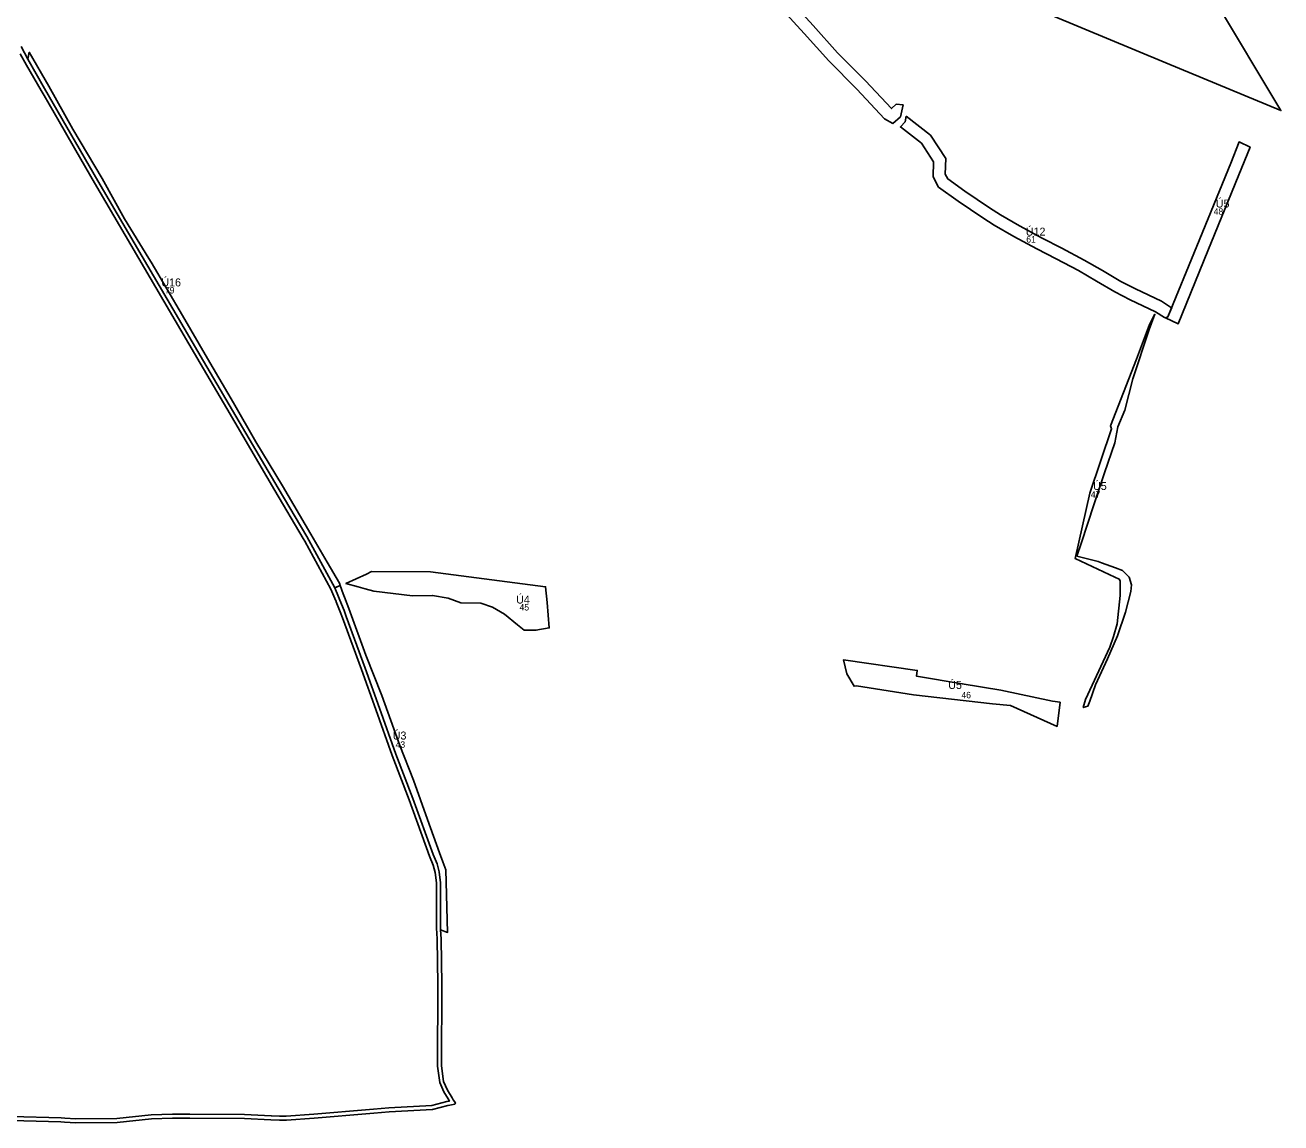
# Model space of a CAD drawing. Extents: x -521621 to -516857, y -1190025 to -1185894.
# Drawn here: x -519468 to -517899, y -1190007 to -1188636 of the extents above; entities that cross this region are included whole.
import ezdxf

# ---------------------------------------------------------------- set-up
doc = ezdxf.new("R2010")
doc.units = 0
for name, color, linetype in [('VPO_id', 7, 'Continuous'), ('VPO_n', 7, 'Continuous'), ('VPS_n', 7, 'Continuous')]:
    doc.layers.add(name, color=color, linetype=linetype)

msp = doc.modelspace()

# ---------------------------------------------------------------- linework, layer by layer
at = {"layer": 'VPO_n'}
for points in [[(-518107.5, -1188434.2), (-518094.9, -1188429), (-518088.8, -1188444.4), (-518071, -1188471), (-517982, -1188604), (-517899.2, -1188742.7), (-518042.7, -1188683.1), (-518186.2, -1188623.6), (-518130.3, -1188487.5)], [(-519313.1, -1188927.4), (-519310.2, -1188932.1), (-519271.2, -1188998.6), (-519239.8, -1189052.4), (-519207.6, -1189107.7), (-519179.5, -1189156.4), (-519146.3, -1189211.4), (-519110.8, -1189271.6), (-519090.3, -1189306.6), (-519075.2, -1189333), (-519074.1, -1189335.9), (-519080.9, -1189338.7), (-519116, -1189274.6), (-519151.5, -1189214.4), (-519245, -1189055.5), (-519376.8, -1188830.4), (-519443.4, -1188715.1), (-519464.3, -1188678.6), (-519462.5, -1188669.8), (-519438.2, -1188712.2), (-519408.1, -1188765.7), (-519371.6, -1188827.4), (-519343.6, -1188877.7)], [(-518367.1, -1188749.7), (-518337, -1188773.2), (-518317.9, -1188802.4), (-518318.6, -1188822), (-518315.3, -1188828), (-518293.9, -1188843.3), (-518263, -1188864), (-518249.5, -1188872.8), (-518225.6, -1188886.7), (-518197.2, -1188902), (-518173, -1188914.4), (-518144.8, -1188929.5), (-518122, -1188942.6), (-518099.3, -1188956), (-518080.9, -1188965.5), (-518048.5, -1188980.7), (-518037.1, -1188988.1), (-518035.5, -1188988.8), (-518040.2, -1189000.4), (-518043.4, -1189001.7), (-518044.4, -1189001.2), (-518055.7, -1188993.9), (-518087.5, -1188979), (-518106.5, -1188969.1), (-518129.5, -1188955.6), (-518152.1, -1188942.6), (-518180, -1188927.7), (-518204.1, -1188915.2), (-518232.9, -1188899.8), (-518257.4, -1188885.6), (-518271.3, -1188876.5), (-518302.4, -1188855.7), (-518326.9, -1188838.2), (-518333.7, -1188825.5), (-518333.1, -1188806.7), (-518348.2, -1188783.4), (-518374.4, -1188763), (-518368.5, -1188756.8)], [(-518040.2, -1189000.4), (-518004.2, -1188912.1), (-517961.8, -1188808.2), (-517951.3, -1188781.9), (-517937.7, -1188788.3), (-517947.9, -1188813.9), (-517990.3, -1188917.8), (-518027.6, -1189009.2), (-518043.4, -1189001.7)], [(-518154, -1189299.1), (-518127.6, -1189305.8), (-518123.3, -1189307.4), (-518105.6, -1189313.9), (-518097, -1189317.1), (-518088.5, -1189325.5), (-518085.7, -1189334.8), (-518086.6, -1189343.3), (-518093.1, -1189369.3), (-518103.4, -1189398.7), (-518115.9, -1189427.4), (-518130.9, -1189459.9), (-518138, -1189480.2), (-518140.3, -1189486.6), (-518146, -1189488.2), (-518143.2, -1189478.3), (-518113, -1189413), (-518108.4, -1189399.5), (-518103.8, -1189383.6), (-518100.1, -1189348.4), (-518100, -1189336.8), (-518100, -1189329.9), (-518101, -1189327.9), (-518106.6, -1189325.3), (-518156.3, -1189301.9), (-518137.7, -1189220.5), (-518110.7, -1189140), (-518111.9, -1189136.4), (-518079.6, -1189053.3), (-518063.3, -1189009.7), (-518056.6, -1188997), (-518063.7, -1189015.9), (-518084.3, -1189077.7), (-518094.1, -1189116.8), (-518102.9, -1189137.6), (-518106.6, -1189157.5), (-518119.4, -1189194.9), (-518133, -1189235.2), (-518148.2, -1189282)], [(-519034.9, -1189318.3), (-518961.3, -1189318.6), (-518817.6, -1189337.4), (-518815.8, -1189357), (-518813, -1189388.8), (-518829.7, -1189391.7), (-518844.5, -1189391.4), (-518852.6, -1189384.9), (-518869, -1189371.4), (-518884.1, -1189363), (-518898.6, -1189357.9), (-518923.6, -1189357.5), (-518939.4, -1189351.8), (-518958.7, -1189348.2), (-518984, -1189348.5), (-519032.1, -1189342.9), (-519043.2, -1189339.8), (-519051.8, -1189337.4), (-519067, -1189333.1), (-519041.3, -1189321.8)], [(-519063.6, -1189364.5), (-519042, -1189422.7), (-519022.2, -1189473.1), (-518999.6, -1189535.6), (-518982.7, -1189579), (-518965.3, -1189627.9), (-518950, -1189669.6), (-518945.9, -1189680.7), (-518942.2, -1189690.9), (-518941.7, -1189706.3), (-518940.1, -1189769.1), (-518948.8, -1189765.7), (-518949.1, -1189707), (-518950.6, -1189693.2), (-518953.1, -1189683.5), (-518958.1, -1189671.9), (-518983.4, -1189601.6), (-519004.7, -1189546.6), (-519025, -1189488.9), (-519042.8, -1189439), (-519066.6, -1189374.5), (-519069.4, -1189367), (-519074.7, -1189354.1), (-519076.3, -1189350.1), (-519080.9, -1189338.7), (-519079.2, -1189338), (-519074.1, -1189335.9), (-519070.4, -1189346), (-519068.7, -1189350.5)], [(-518237, -1189485.8), (-518259.4, -1189483.4), (-518358.1, -1189472.5), (-518429.1, -1189461.3), (-518432.4, -1189461.6), (-518441.4, -1189446.2), (-518445.5, -1189428.6), (-518353.4, -1189441.9), (-518354.2, -1189449.1), (-518297.2, -1189458.4), (-518248.8, -1189466.6), (-518184.3, -1189480.1), (-518175, -1189481.7), (-518178.7, -1189511.8)]]:
    msp.add_lwpolyline(points, close=True, dxfattribs=at)
msp.add_lwpolyline([(-518510.4, -1188606.8), (-518483.5, -1188636.3), (-518453, -1188670.4), (-518417.9, -1188705.7), (-518385.7, -1188740.2), (-518379.8, -1188734.7), (-518371.1, -1188735.6), (-518374.5, -1188750.3), (-518383.7, -1188758.8), (-518394.5, -1188752.8), (-518428.7, -1188716.1), (-518463.9, -1188680.7), (-518494.6, -1188646.3), (-518521.3, -1188617.2)], dxfattribs=at)
at = {"layer": 'VPS_n'}
for points in [[(-519474.1, -1188671.9), (-519465.9, -1188685.9), (-519447.7, -1188717.6), (-519444, -1188724), (-519425.3, -1188756.4), (-519398.3, -1188803.3), (-519381.1, -1188833), (-519249.3, -1189058), (-519215.9, -1189114.9), (-519155.8, -1189217), (-519120.4, -1189277.1), (-519118.4, -1189280.6), (-519085.8, -1189340.2), (-519081, -1189351.9), (-519080.9, -1189352), (-519079.3, -1189355.9), (-519079.3, -1189356), (-519074.1, -1189368.8), (-519071.3, -1189376.3), (-519047.5, -1189440.7), (-519029.7, -1189490.5), (-519009.4, -1189548.3), (-518988, -1189603.3), (-518962.8, -1189673.7), (-518957.9, -1189685.1), (-518955.5, -1189694.1), (-518954.1, -1189707.2), (-518953.8, -1189763.8), (-518953, -1189777.1), (-518952.2, -1189834), (-518952.8, -1189935.9), (-518949.8, -1189956.5), (-518944.8, -1189968.3), (-518939.5, -1189976.9), (-518937.8, -1189979.7), (-518940.8, -1189980.3), (-518959.9, -1189985.1), (-519013.4, -1189988.1), (-519032.4, -1189989.7), (-519037.4, -1189990.2), (-519107.2, -1189996.1), (-519141.6, -1189998.5), (-519150, -1189998.5), (-519160.2, -1189998), (-519160.5, -1189998), (-519193.6, -1189996.5), (-519262.1, -1189996.2), (-519283.7, -1189996.2), (-519310.3, -1189997), (-519353, -1190001.3), (-519404.3, -1190001.9), (-519418.2, -1190001.1), (-519422.8, -1190000.8), (-519484.8, -1189998.9)], [(-519245, -1189055.5), (-519376.8, -1188830.4), (-519443.4, -1188715.1), (-519464.3, -1188678.6), (-519472.8, -1188662.7)], [(-519484.8, -1190003.9), (-519423, -1190005.8), (-519418.5, -1190006.1), (-519404.5, -1190006.9), (-519352.8, -1190006.3), (-519310, -1190002), (-519283.6, -1190001.2), (-519262.1, -1190001.2), (-519193.8, -1190001.4), (-519160.7, -1190003), (-519150.2, -1190003.5), (-519141.4, -1190003.5), (-519106.8, -1190001), (-519037.2, -1189995.2), (-519032.2, -1189994.7), (-519013.1, -1189993.1), (-518959.1, -1189990.1), (-518939.7, -1189985.2), (-518937.4, -1189984.8), (-518931.1, -1189983.5), (-518930.3, -1189982), (-518933, -1189978), (-518934.4, -1189975.6), (-518940.3, -1189966), (-518945, -1189955.1), (-518947.8, -1189935.6), (-518947.2, -1189834), (-518948, -1189776.9), (-518948.8, -1189765.7), (-518949.1, -1189707), (-518950.6, -1189693.2), (-518953.1, -1189683.5), (-518958.1, -1189671.9), (-518983.4, -1189601.6), (-519004.7, -1189546.6), (-519025, -1189488.9), (-519042.8, -1189439), (-519066.6, -1189374.5), (-519069.4, -1189367), (-519074.7, -1189354.1), (-519076.3, -1189350.1), (-519080.9, -1189338.7), (-519116, -1189274.6), (-519151.5, -1189214.4), (-519245, -1189055.5)]]:
    msp.add_lwpolyline(points, dxfattribs=at)

# ---------------------------------------------------------------- texts
at = {"layer": 'VPO_id'}
for s, p in [('48', (-517983.1, -1188872.7)), ('61', (-518217.2, -1188907.5)), ('79', (-519293.1, -1188971.1)), ('47', (-518136.6, -1189226.1)), ('45', (-518850.2, -1189367)), ('46', (-518298.2, -1189476.6)), ('43', (-519005, -1189538.4))]:
    msp.add_text(s, height=8, dxfattribs=at).set_placement(p)
at = {"layer": 'VPO_n'}
for s, p in [('Ú5', (-517980.5, -1188863.8)), ('Ú12', (-518217.8, -1188898.9)), ('Ú16', (-519297.6, -1188962.3)), ('Ú5', (-518133.8, -1189216.5)), ('Ú4', (-518854.4, -1189358.3)), ('Ú5', (-518314.7, -1189465)), ('Ú3', (-519008.6, -1189528.2))]:
    msp.add_text(s, height=10, dxfattribs=at).set_placement(p)

doc.saveas('drawing.dxf')
